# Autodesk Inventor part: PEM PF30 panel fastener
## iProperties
Author: John A. Hunter
Shininess: 64.0
Angle Display Precision: 2
Document Length Units: 11272
Document Angle Units: 11286
Document Time Units: 11279
Document Mass Units: 11290
Document Length Units Precision: 3
Document Angle Units Precision: 2
Compacted: True
PropertySet Name: _Private Model Information
Created: 2002-08
Part Number: PEM PF30 panel fastener
Material: Steel, High Strength Low Alloy
Description: PF30-440-30
Document SubType Name: Modeling
Designer: John A. Hunter
Control State: 0
Master: False
Checked Out: False
PropertySet Name: Design Tracking Control
Density: 0.0
Volumn: 0.0
Area: 0.0
PropertySet Name: Model Information
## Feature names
1. Extrusion1
2. Extrusion2
3. Extrusion3
4. Chamfer1
5. Extrusion4
